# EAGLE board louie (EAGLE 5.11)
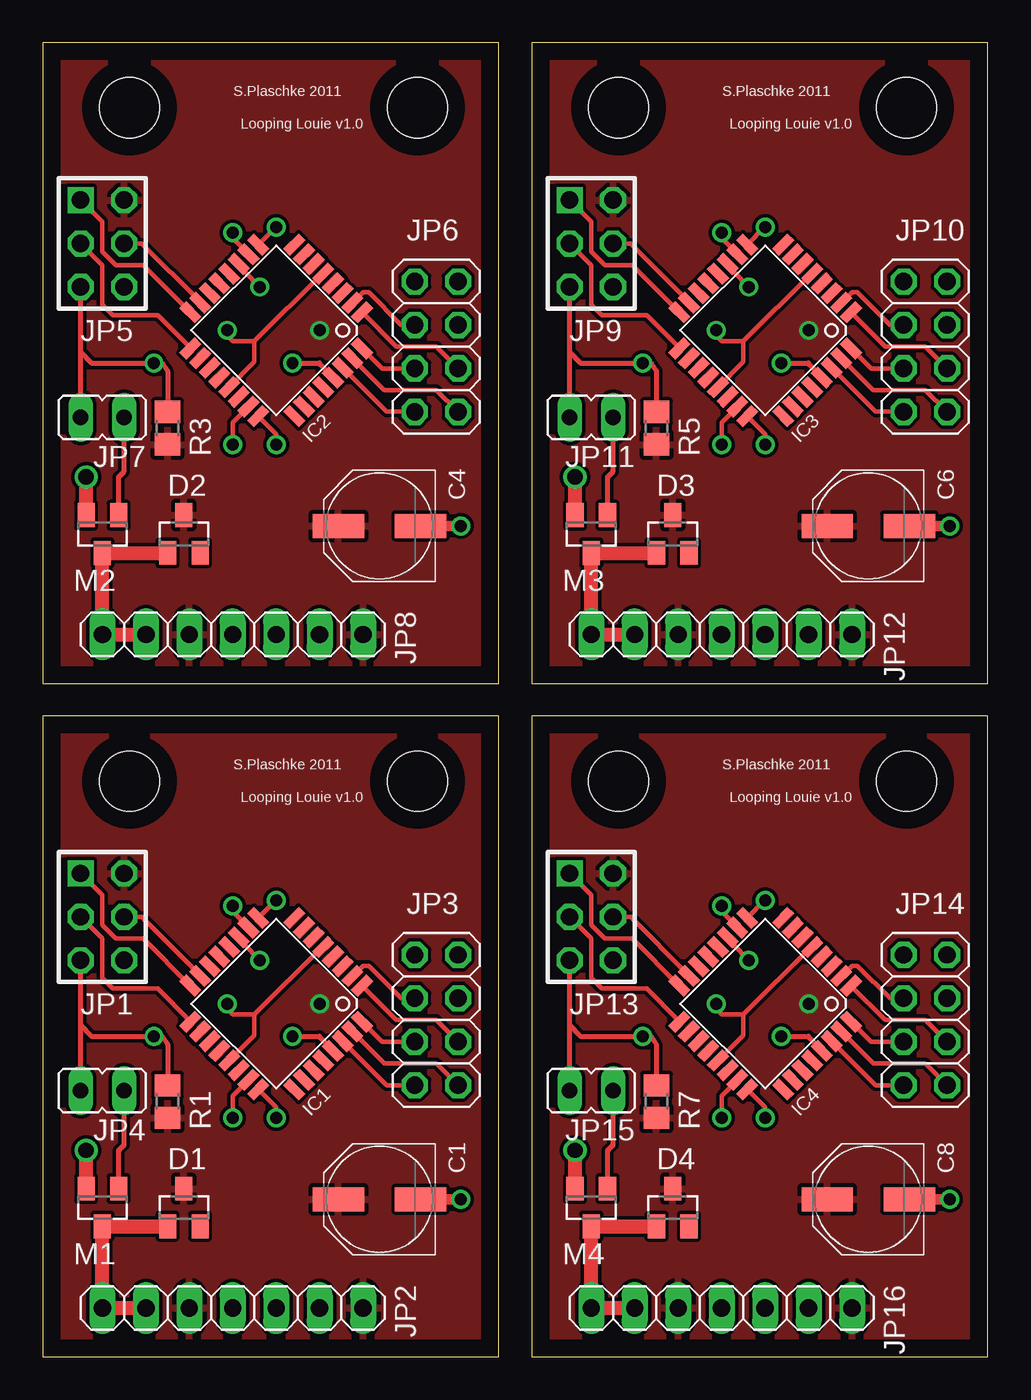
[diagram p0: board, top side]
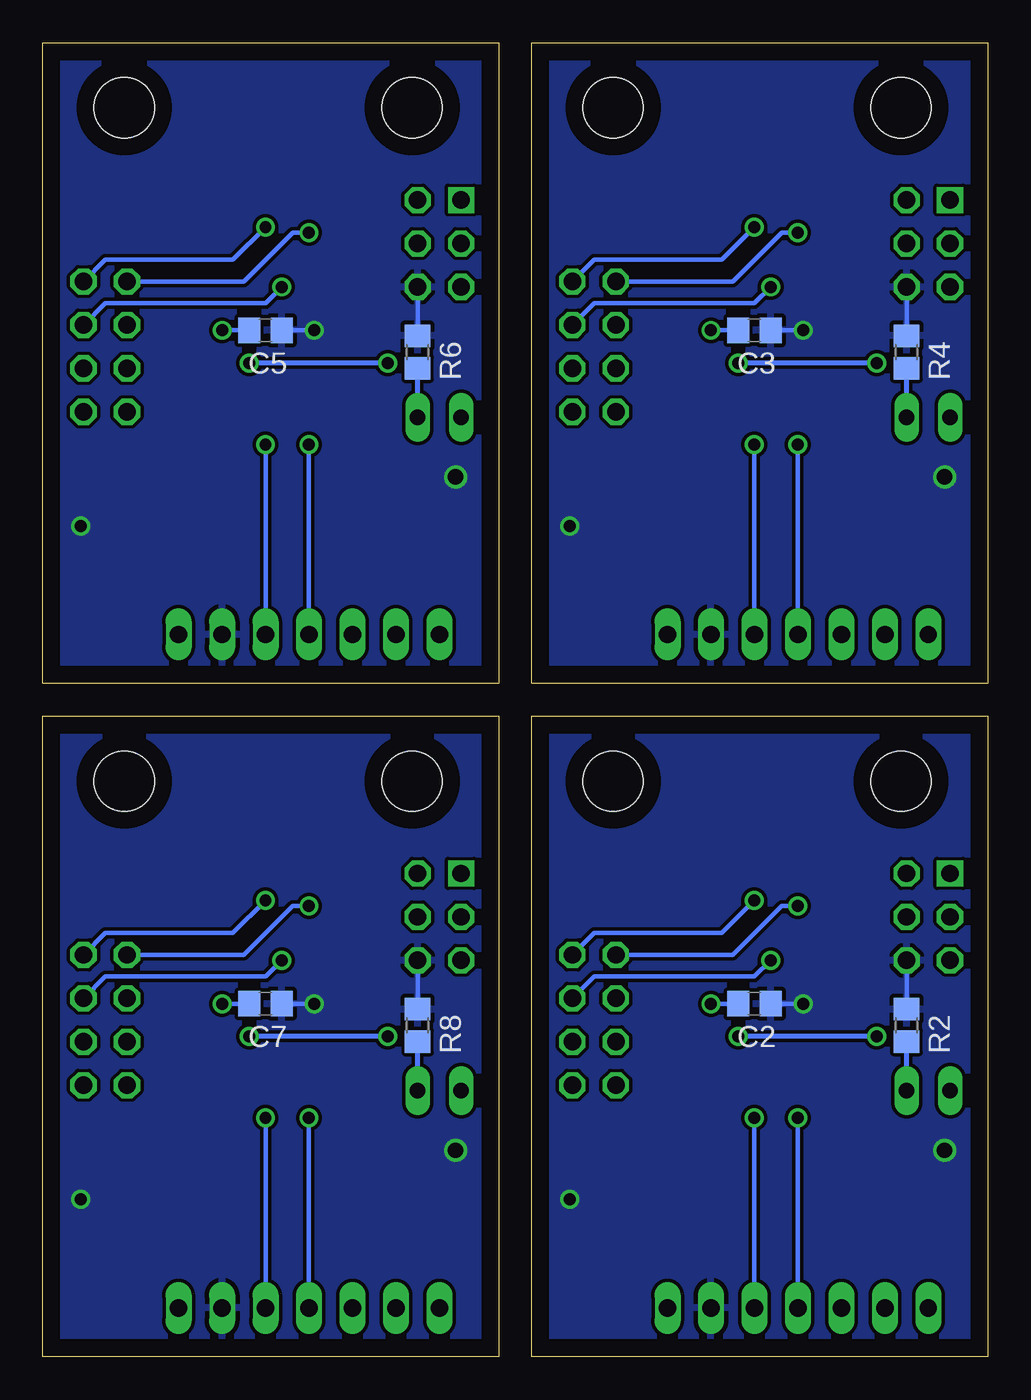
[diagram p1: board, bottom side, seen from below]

Size 55.23 x 76.82 mm. Coordinates in mm from the lower left corner, seen from the top.
Outline: 26.66,0 26.66,37.45 0,37.45 0,0 26.66,0
Outline: 26.66,39.37 26.66,76.82 0,76.82 0,39.37 26.66,39.37
Outline: 55.23,39.37 55.23,76.82 28.57,76.82 28.57,39.37 55.23,39.37
Outline: 55.23,0 55.23,37.45 28.57,37.45 28.57,0 55.23,0
Copper layers (1*16): Top 0.035mm / dielectric 1.5mm / Bottom 0.035mm
Design rules "default": minimum track width 10mil, minimum drill 24mil, track to track 8mil, track to pad 8mil, pad to pad 8mil, via to via 8mil, smd to smd 8mil, copper to edge 40mil, drill to drill 8mil, minimum pad ring 10mil, minimum via ring 8mil, stop-mask expansion 4mil, vias tented up to drill 0mil, thermal gap 10mil
Holes 3.5 mm at 5.07,33.66 21.9,33.66 5.07,73.03 21.9,73.03 33.65,73.03 50.47,73.03 33.65,33.66 50.47,33.66

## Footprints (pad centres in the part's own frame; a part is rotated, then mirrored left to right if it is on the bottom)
PANASONIC_D = smd 3 x 1.4: + 2.4,0; - -2.4,0
C0805 = smd 1.3 x 1.5: 1 -0.95,0; 2 0.95,0
SOT23 = smd 1 x 1.4: 1 -0.95,-1.1; 2 0.95,-1.1; 3 0,1.1
TQFP32-08 = smd 1.27 x 0.559: 1 -4.293,2.8; 2 -4.293,2; 3 -4.293,1.2; 4 -4.293,0.4; 5 -4.293,-0.4; 6 -4.293,-1.2; 7 -4.293,-2; 8 -4.293,-2.8; 17 4.293,-2.8; 18 4.293,-2; 19 4.293,-1.2; 20 4.293,-0.4; 21 4.293,0.4; 22 4.293,1.2; 23 4.293,2; 24 4.293,2.8 | smd 0.559 x 1.27: 9 -2.8,-4.293; 10 -2,-4.293; 11 -1.2,-4.293; 12 -0.4,-4.293; 13 0.4,-4.293; 14 1.2,-4.293; 15 2,-4.293; 16 2.8,-4.293; 25 2.8,4.293; 26 2,4.293; 27 1.2,4.293; 28 0.4,4.293; 29 -0.4,4.293; 30 -1.2,4.293; 31 -2,4.293; 32 -2.8,4.293
AVR-ISP-6 = drill 1.016 square: 1 -2.54,-1.27 | drill 1.016 octagon: 2 -2.54,1.27; 3 0,-1.27; 4 0,1.27; 5 2.54,-1.27; 6 2.54,1.27
1X07 = drill 1.016 long: 1 -7.62,0; 2 -5.08,0; 3 -2.54,0; 4 0,0; 5 2.54,0; 6 5.08,0; 7 7.62,0
2X04 = drill 1.016 octagon: 1 -3.81,-1.27; 2 -3.81,1.27; 3 -1.27,-1.27; 4 -1.27,1.27; 5 1.27,-1.27; 6 1.27,1.27; 7 3.81,-1.27; 8 3.81,1.27
JP1 = drill 0.914 long: 1 0,-1.27; 2 0,1.27
R0805 = smd 1.3 x 1.5: 1 -0.95,0; 2 0.95,0

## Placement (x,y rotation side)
C1  100u  [PANASONIC_D]  19.67,9.21 180 top
C2  100n  [C0805]  13.64,20.64 180 bottom
C3  100n  [C0805]  13.64,60.01 180 bottom
C4  100u  [PANASONIC_D]  19.67,48.58 180 top
C5  100n  [C0805]  42.22,60.01 180 bottom
C6  100u  [PANASONIC_D]  48.25,48.58 180 top
C7  100n  [C0805]  42.22,20.64 180 bottom
C8  100u  [PANASONIC_D]  48.25,9.21 180 top
D1  BAT54  [SOT23]  8.25,8.73 0 top
D2  BAT54  [SOT23]  8.25,48.1 0 top
D3  BAT54  [SOT23]  36.82,48.1 0 top
D4  BAT54  [SOT23]  36.82,8.73 0 top
IC1  MEGA8-AI  [TQFP32-08]  13.64,20.64 225 top
IC2  MEGA8-AI  [TQFP32-08]  13.64,60.01 225 top
IC3  MEGA8-AI  [TQFP32-08]  42.22,60.01 225 top
IC4  MEGA8-AI  [TQFP32-08]  42.22,20.64 225 top
JP1  ISP  [AVR-ISP-6]  3.48,25.72 270 top
JP2  [1X07]  11.1,2.86 180 top
JP3  [2X04]  23.01,19.68 270 top
JP4  [JP1]  3.48,15.56 90 top
JP5  ISP  [AVR-ISP-6]  3.48,65.09 270 top
JP6  [2X04]  23.01,59.05 270 top
JP7  [JP1]  3.48,54.93 90 top
JP8  [1X07]  11.1,42.23 180 top
JP9  ISP  [AVR-ISP-6]  32.06,65.09 270 top
JP10  [2X04]  51.58,59.05 270 top
JP11  [JP1]  32.06,54.93 90 top
JP12  [1X07]  39.68,42.23 180 top
JP13  ISP  [AVR-ISP-6]  32.06,25.72 270 top
JP14  [2X04]  51.58,19.68 270 top
JP15  [JP1]  32.06,15.56 90 top
JP16  [1X07]  39.68,2.86 180 top
M1  IRLML2502  [SOT23]  3.48,8.73 180 top
M2  IRLML2502  [SOT23]  3.48,48.1 180 top
M3  IRLML2502  [SOT23]  32.06,48.1 180 top
M4  IRLML2502  [SOT23]  32.06,8.73 180 top
R1  10k  [R0805]  7.29,14.92 270 top
R2  10k  [R0805]  4.75,19.37 270 bottom
R3  10k  [R0805]  7.29,54.29 270 top
R4  10k  [R0805]  4.75,58.74 270 bottom
R5  10k  [R0805]  35.87,54.29 270 top
R6  10k  [R0805]  33.33,58.74 270 bottom
R7  10k  [R0805]  35.87,14.92 270 top
R8  10k  [R0805]  33.33,19.37 270 bottom

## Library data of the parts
C1-C8 R1-R8 = rcl
D1-D4 = diode
IC1-IC4 JP1 JP5 JP9 JP13 = avr-7
JP2 JP3 JP6 JP8 JP10 JP12 JP14 JP16 = pinhead
JP4 JP7 JP11 JP15 = jumper
M1-M4 = transistor-power

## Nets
+5V: C1.+ C2.2 D1.3 IC1.4 IC1.6 IC1.18 IC1.20 JP1.2 JP2.1 JP2.5 R1.2
+5V1: C3.2 C4.+ D2.3 IC2.4 IC2.6 IC2.18 IC2.20 JP5.2 JP8.1 JP8.5 R3.2
+5V2: C5.2 C6.+ D3.3 IC3.4 IC3.6 IC3.18 IC3.20 JP9.2 JP12.1 JP12.5 R5.2
+5V3: C7.2 C8.+ D4.3 IC4.4 IC4.6 IC4.18 IC4.20 JP13.2 JP16.1 JP16.5 R7.2
GND: C1.- C2.1 IC1.5 IC1.21 JP1.6 JP2.2 M1.2 R2.1
GND1: C3.1 C4.- IC2.5 IC2.21 JP5.6 JP8.2 M2.2 R4.1
GND2: C5.1 C6.- IC3.5 IC3.21 JP9.6 JP12.2 M3.2 R6.1
GND3: C7.1 C8.- IC4.5 IC4.21 JP13.6 JP16.2 M4.2 R8.1
N$1: IC1.23 JP2.4
N$2: IC1.17 JP1.3
N$3: IC1.29 JP1.5 JP4.2 R1.1
N$4: IC1.3
N$5: IC1.31 JP3.8
N$6: IC1.16 JP1.1
N$7: IC1.15 JP1.4
N$8: IC1.1 JP3.6
N$9: IC1.9 JP3.2
N$10: IC1.11 JP3.4
N$11: IC1.10 JP3.1
N$12: IC1.2 JP3.3
N$13: IC1.32 JP3.5
N$14: IC1.30 JP3.7
N$15: JP4.1 M1.1 R2.2
N$16: IC1.24 JP2.3
N$17: IC2.29 JP5.5 JP7.2 R3.1
N$18: D1.1 JP2.6 JP2.7 M1.3
N$19: IC2.3
N$20: IC2.17 JP5.3
N$21: IC2.16 JP5.1
N$22: IC2.15 JP5.4
N$23: JP7.1 M2.1 R4.2
N$24: D2.1 JP8.6 JP8.7 M2.3
N$25: IC2.31 JP6.8
N$26: IC2.1 JP6.6
N$27: IC2.9 JP6.2
N$28: IC2.11 JP6.4
N$29: IC2.10 JP6.1
N$30: IC2.32 JP6.5
N$31: IC2.30 JP6.7
N$32: IC2.2 JP6.3
N$33: IC2.24 JP8.3
N$34: IC2.23 JP8.4
N$35: IC3.29 JP9.5 JP11.2 R5.1
N$36: IC3.3
N$37: IC3.17 JP9.3
N$38: IC3.16 JP9.1
N$39: IC3.15 JP9.4
N$40: JP11.1 M3.1 R6.2
N$41: D3.1 JP12.6 JP12.7 M3.3
N$42: IC3.31 JP10.8
N$43: IC3.1 JP10.6
N$44: IC3.9 JP10.2
N$45: IC3.11 JP10.4
N$46: IC3.10 JP10.1
N$47: IC3.32 JP10.5
N$48: IC3.30 JP10.7
N$49: IC3.2 JP10.3
N$50: IC3.24 JP12.3
N$51: IC3.23 JP12.4
N$52: IC4.29 JP13.5 JP15.2 R7.1
N$53: IC4.3
N$54: IC4.17 JP13.3
N$55: IC4.16 JP13.1
N$56: IC4.15 JP13.4
N$57: JP15.1 M4.1 R8.2
N$58: D4.1 JP16.6 JP16.7 M4.3
N$59: IC4.31 JP14.8
N$60: IC4.1 JP14.6
N$61: IC4.9 JP14.2
N$62: IC4.11 JP14.4
N$63: IC4.10 JP14.1
N$64: IC4.32 JP14.5
N$65: IC4.30 JP14.7
N$66: IC4.2 JP14.3
N$67: IC4.24 JP16.3
N$68: IC4.23 JP16.4

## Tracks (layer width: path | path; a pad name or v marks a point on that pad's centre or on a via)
+5V  (via drill 0.7)
  Bottom 0.254: C2.2 v16.18,20.64
  pour Top: 0.31,0.32 0.31,37.15 26.02,37.15 26.02,0.32
+5V1  (via drill 0.7)
  Bottom 0.254: C3.2 v16.18,60.01
  pour Top: 0.31,39.69 0.31,76.52 26.02,76.52 26.02,39.69
+5V2  (via drill 0.7)
  Bottom 0.254: C5.2 v44.76,60.01
  pour Top: 28.88,39.69 28.88,76.52 54.6,76.52 54.6,39.69
+5V3  (via drill 0.7)
  Bottom 0.254: C7.2 v44.76,20.64
  pour Top: 28.88,0.32 28.88,37.15 54.6,37.15 54.6,0.32
GND  (via drill 0.7, 0.9)
  Top 0.254: IC1.5 16.33,23.96 12.37,20 | 12.37,20 12.37,18.8 IC1.21 | v10.79,20.64 10.79,20.32 11.1,20 12.37,20
  Top 0.305: IC1.21 | IC1.5
  Top 0.61: C1.- v24.44,9.21
  Top 0.813: M1.2 v2.53,12.06
  Bottom 0.254: R2.1 JP1.6 | v10.79,20.64 C2.1
  pour Bottom: 0.31,0.32 0.31,37.15 26.02,37.15 26.02,0.32
GND1  (via drill 0.7, 0.9)
  Top 0.254: IC2.5 16.33,63.33 12.37,59.37 | 12.37,59.37 12.37,58.17 IC2.21 | v10.79,60.01 10.79,59.69 11.1,59.37 12.37,59.37
  Top 0.61: C4.- v24.44,48.58
  Top 0.813: M2.2 v2.53,51.43 v2.53,51.44
  Bottom 0.254: R4.1 JP5.6 | v10.79,60.01 C3.1
  pour Bottom: 0.31,39.69 0.31,76.52 26.02,76.52 26.02,39.69
GND2  (via drill 0.7, 0.9)
  Top 0.254: IC3.5 44.9,63.33 40.95,59.37 | 40.95,59.37 40.95,58.17 IC3.21 | v39.36,60.01 39.36,59.69 39.68,59.37 40.95,59.37
  Top 0.61: C6.- v53.01,48.58
  Top 0.813: M3.2 v31.11,51.43 v31.1,51.44
  Bottom 0.254: R6.1 JP9.6 | v39.36,60.01 C5.1
  pour Bottom: 28.88,39.69 28.88,76.52 54.6,76.52 54.6,39.69
GND3  (via drill 0.7, 0.9)
  Top 0.254: IC4.5 44.9,23.96 40.95,20 | 40.95,20 40.95,18.8 IC4.21 | v39.36,20.64 39.36,20.32 39.68,20 40.95,20
  Top 0.61: C8.- v53.01,9.21
  Top 0.813: M4.2 v31.11,12.06 v31.1,12.06
  Bottom 0.254: R8.1 JP13.6 | v39.36,20.64 C7.1
  pour Bottom: 28.88,0.32 28.88,37.15 54.6,37.15 54.6,0.32
N$1  (via drill 0.7)
  Top 0.254: IC1.23 12.02,16.16 11.9,16.03 11.1,15.24 v11.1,13.97
  Top 0.305: IC1.23 12.02,16.16 11.9,16.03
  Bottom 0.254: JP2.4 v11.1,13.97
N$2
  Top 0.254: IC1.17 8.63,19.62 6.72,21.52 4.1,21.52 3.48,22.15 3.48,24.45 JP1.3
  Top 0.305: IC1.17
N$3  (via drill 0.7)
  Top 0.254: 16.18,18.73 16.18,18.66 | v6.5,18.73 6.98,18.73
  Top 0.305: JP4.2 2.21,19.37 | v14.6,18.73 16.18,18.73 | 16.18,18.66 IC1.29 | R1.1 7.29,18.26 6.98,18.73 | 2.21,19.37 2.85,18.73 v6.5,18.73 | 2.21,19.37 JP1.5 | IC1.29
  Bottom 0.305: v6.5,18.73 v14.6,18.73
N$5
  Top 0.254: 18.41,18.73 IC1.31 19.96,17.14 23.01,17.14 JP3.8
  Top 0.305: IC1.31
N$6
  Top 0.254: 8.62,21.69 5.86,24.45 4.28,24.45 3.48,25.24 3.48,26.99 JP1.1 | IC1.16
  Top 0.305: 8.62,21.69 IC1.16
N$7
  Top 0.254: IC1.15 9.16,22.26 9.16,22.34 5.78,25.72 JP1.4
  Top 0.305: IC1.15
N$8
  Top 0.254: JP3.6 23.01,19.68 20.67,19.68 IC1.1 | IC1.1
N$9  (via drill 0.7)
  Top 0.254: v13.64,26.67 13.6,26.67 IC1.9
  Top 0.305: IC1.9
  Bottom 0.254: JP3.2 23.01,24.77 15.55,24.77 v13.64,26.67
N$10  (via drill 0.7)
  Top 0.254: v12.69,23.18 11.74,24.13 11.74,24.24 11.63,24.34 IC1.11 | IC1.11
  Bottom 0.254: JP3.4 23.01,22.23 13.64,22.23 v12.69,23.18
N$11  (via drill 0.7)
  Top 0.254: IC1.10 12.02,25.12 11.58,25.56 11.1,26.04 v11.1,26.35
  Top 0.305: IC1.10 12.02,25.12 11.58,25.56
  Bottom 0.254: v11.1,26.35 12.05,26.35 14.91,23.5 JP3.1
N$12
  Top 0.254: JP3.3 20.94,20.95 19.04,22.86 18.72,22.86 18.12,22.26 IC1.2
  Top 0.305: IC1.2
N$13
  Top 0.254: JP3.5 19.83,18.41 IC1.32
  Top 0.305: IC1.32
N$14
  Top 0.254: 17.53,18.34 IC1.30 20.1,15.88 JP3.7
  Top 0.305: IC1.30
N$15
  Top 0.305: JP4.1 4.75,12.38 4.44,12.06 M1.1
  Bottom 0.305: JP4.1 R2.2
N$16  (via drill 0.7)
  Top 0.254: v13.64,13.97 13.64,14.57 IC1.24
  Top 0.305: IC1.24
  Bottom 0.254: JP2.3 v13.64,13.97
N$17  (via drill 0.7)
  Top 0.254: 16.18,58.1 16.18,58.03 | v6.5,58.1 6.98,58.1
  Top 0.305: JP7.2 2.21,58.74 | v14.6,58.1 16.18,58.1 | 16.18,58.03 IC2.29 | R3.1 7.29,57.63 6.98,58.1 | 2.21,58.74 2.85,58.1 v6.5,58.1 | 2.21,58.74 JP5.5
  Bottom 0.305: v6.5,58.1 v14.6,58.1
N$18
  Top 0.813: D1.1 M1.3 JP2.7 JP2.6
N$20
  Top 0.254: IC2.17 8.63,58.99 6.72,60.9 4.1,60.9 3.48,61.52 3.48,63.82 JP5.3
N$21
  Top 0.254: IC2.16 8.62,61.06 5.86,63.82 4.28,63.82 3.48,64.61 3.48,66.36 JP5.1
N$22
  Top 0.254: IC2.15 9.16,61.63 9.16,61.71 5.78,65.09 JP5.4
N$23
  Top 0.305: JP7.1 4.75,51.75 4.44,51.44 M2.1
  Bottom 0.305: JP7.1 R4.2
N$24
  Top 0.813: D2.1 M2.3 JP8.7 JP8.6
N$25
  Top 0.254: 18.41,58.1 IC2.31 19.96,56.52 23.01,56.52 JP6.8
N$26
  Top 0.254: JP6.6 23.01,59.05 20.67,59.05 IC2.1
N$27  (via drill 0.7)
  Top 0.254: v13.64,66.04 13.6,66.04 IC2.9
  Bottom 0.254: JP6.2 23.01,64.14 15.55,64.14 v13.64,66.04
N$28  (via drill 0.7)
  Top 0.254: v12.69,62.55 11.74,63.5 11.74,63.61 IC2.11
  Bottom 0.254: JP6.4 23.01,61.59 13.64,61.59 v12.69,62.55
N$29  (via drill 0.7)
  Top 0.254: IC2.10 12.02,64.49 11.1,65.41 v11.1,65.72
  Bottom 0.254: v11.1,65.72 12.05,65.72 14.91,62.87 JP6.1
N$30
  Top 0.254: JP6.5 19.83,57.78 IC2.32
N$31
  Top 0.254: 17.53,57.71 IC2.30 20.1,55.24 JP6.7
N$32
  Top 0.254: JP6.3 20.94,60.33 19.04,62.23 18.72,62.23 18.12,61.63 IC2.2
N$33  (via drill 0.7)
  Top 0.254: v13.64,53.34 13.64,53.94 IC2.24
  Bottom 0.254: JP8.3 v13.64,53.34
N$34  (via drill 0.7)
  Top 0.254: IC2.23 12.02,55.53 11.1,54.61 v11.1,53.34
  Bottom 0.254: JP8.4 v11.1,53.34
N$35  (via drill 0.7)
  Top 0.254: 44.76,58.1 44.76,58.03 | v35.07,58.1 35.55,58.1
  Top 0.305: JP11.2 30.79,58.74 | v43.17,58.1 44.76,58.1 | 44.76,58.03 IC3.29 | R5.1 35.87,57.63 35.55,58.1 | 30.79,58.74 31.42,58.1 v35.07,58.1 | 30.79,58.74 JP9.5
  Bottom 0.305: v35.07,58.1 v43.17,58.1
N$37
  Top 0.254: IC3.17 37.2,58.99 35.3,60.9 32.68,60.9 32.06,61.52 32.06,63.82 JP9.3
N$38
  Top 0.254: IC3.16 34.44,63.82 32.85,63.82 32.06,64.61 32.06,66.36 JP9.1
N$39
  Top 0.254: IC3.15 37.74,61.63 37.74,61.71 34.36,65.09 JP9.4
N$40
  Top 0.305: JP11.1 33.33,51.75 33.01,51.44 M3.1
  Bottom 0.305: JP11.1 R6.2
N$41
  Top 0.813: D3.1 M3.3 JP12.7 JP12.6
N$42
  Top 0.254: 46.98,58.1 IC3.31 48.54,56.52 51.58,56.52 JP10.8
N$43
  Top 0.254: JP10.6 51.58,59.05 49.24,59.05 IC3.1
N$44  (via drill 0.7)
  Top 0.254: v42.22,66.04 42.18,66.04 IC3.9
  Bottom 0.254: JP10.2 51.58,64.14 44.12,64.14 v42.22,66.04
N$45  (via drill 0.7)
  Top 0.254: v41.27,62.55 40.31,63.5 40.31,63.61 IC3.11
  Bottom 0.254: JP10.4 51.58,61.59 42.22,61.59 v41.27,62.55
N$46  (via drill 0.7)
  Top 0.254: IC3.10 40.6,64.49 39.68,65.41 v39.68,65.72
  Bottom 0.254: v39.68,65.72 40.63,65.72 43.49,62.87 JP10.1
N$47
  Top 0.254: JP10.5 48.41,57.78 47.24,58.95 IC3.32
N$48
  Top 0.254: 46.1,57.71 IC3.30 48.68,55.24 JP10.7
N$49
  Top 0.254: JP10.3 49.52,60.33 47.62,62.23 47.3,62.23 46.7,61.63 IC3.2
N$50  (via drill 0.7)
  Top 0.254: v42.22,53.34 42.22,53.94 IC3.24
  Bottom 0.254: JP12.3 v42.22,53.34
N$51  (via drill 0.7)
  Top 0.254: IC3.23 40.6,55.53 39.68,54.61 v39.68,53.34
  Bottom 0.254: JP12.4 v39.68,53.34
N$52  (via drill 0.7)
  Top 0.254: 44.76,18.73 44.76,18.66 | v35.07,18.73 35.55,18.73
  Top 0.305: JP15.2 30.79,19.37 | v43.17,18.73 44.76,18.73 | 44.76,18.66 IC4.29 | R7.1 35.87,18.26 35.55,18.73 | 30.79,19.37 31.42,18.73 v35.07,18.73 | 30.79,19.37 JP13.5
  Bottom 0.305: v35.07,18.73 v43.17,18.73
N$54
  Top 0.254: IC4.17 37.2,19.62 35.3,21.52 32.68,21.52 32.06,22.15 32.06,24.45 JP13.3
N$55
  Top 0.254: IC4.16 34.44,24.45 32.85,24.45 32.06,25.24 32.06,26.99 JP13.1
N$56
  Top 0.254: IC4.15 37.74,22.26 37.74,22.34 34.36,25.72 JP13.4
N$57
  Top 0.305: JP15.1 33.33,12.38 33.01,12.06 M4.1
  Bottom 0.305: JP15.1 R8.2
N$58
  Top 0.813: D4.1 M4.3 JP16.7 JP16.6
N$59
  Top 0.254: 46.98,18.73 IC4.31 48.54,17.14 51.58,17.14 JP14.8
N$60
  Top 0.254: JP14.6 51.58,19.68 49.24,19.68 IC4.1
N$61  (via drill 0.7)
  Top 0.254: v42.22,26.67 42.18,26.67 IC4.9
  Bottom 0.254: JP14.2 51.58,24.77 44.12,24.77 v42.22,26.67
N$62  (via drill 0.7)
  Top 0.254: v41.27,23.18 40.31,24.13 40.31,24.24 IC4.11
  Bottom 0.254: JP14.4 51.58,22.23 42.22,22.23 v41.27,23.18
N$63  (via drill 0.7)
  Top 0.254: IC4.10 40.6,25.12 39.68,26.04 v39.68,26.35
  Bottom 0.254: v39.68,26.35 40.63,26.35 43.49,23.5 JP14.1
N$64
  Top 0.254: JP14.5 48.41,18.41 47.24,19.58 IC4.32
N$65
  Top 0.254: 46.1,18.34 IC4.30 48.68,15.88 JP14.7
N$66
  Top 0.254: JP14.3 49.52,20.95 47.62,22.86 47.3,22.86 46.7,22.26 IC4.2
N$67  (via drill 0.7)
  Top 0.254: v42.22,13.97 42.22,14.57 IC4.24
  Bottom 0.254: JP16.3 v42.22,13.97
N$68  (via drill 0.7)
  Top 0.254: IC4.23 40.6,16.16 39.68,15.24 v39.68,13.97
  Bottom 0.254: JP16.4 v39.68,13.97

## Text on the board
tNames: S.Plaschke 2011 | S.Plaschke 2011 | Looping Louie v1.0 | Looping Louie v1.0 | S.Plaschke 2011 | S.Plaschke 2011 | Looping Louie v1.0 | Looping Louie v1.0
